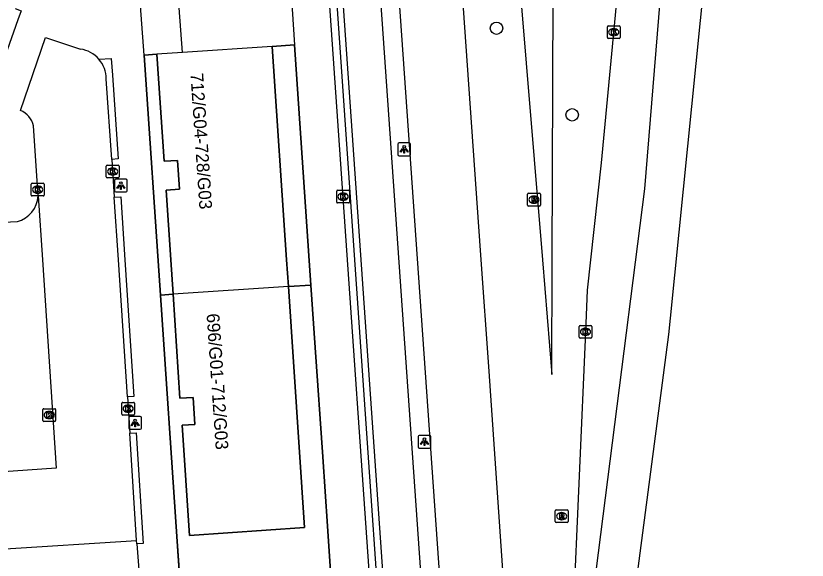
# Model space of a CAD drawing. Extents: x 161253 to 161848, y 384872 to 385383.
# Drawn here: x 161781 to 161843, y 385226.4 to 385269.1 of the extents above; entities that cross this region are included whole.
import ezdxf

# ---------------------------------------------------------------- set-up
doc = ezdxf.new("R2010")
doc.units = 0
for name, color, linetype in [('IMGEO_Berm_groen', 7, 'Continuous'), ('IMGEO_Boom', 7, 'Continuous'), ('IMGEO_Fietspad_open', 7, 'Continuous'), ('IMGEO_Groenvoorziening', 7, 'Continuous'), ('IMGEO_Kolk', 7, 'Continuous'), ('IMGEO_Lichtpunt', 7, 'Continuous'), ('IMGEO_Muur', 7, 'Continuous'), ('IMGEO_Pand', 7, 'Continuous'), ('IMGEO_Pand_nummerreeks', 7, 'Continuous'), ('IMGEO_Pand_overbouw', 7, 'Continuous'), ('IMGEO_Rijbaan_lokaal_open', 7, 'Continuous'), ('IMGEO_Rijbaan_regionaal_gesloten', 7, 'Continuous'), ('IMGEO_Rioolput', 7, 'Continuous'), ('IMGEO_Voetpad_open', 7, 'Continuous')]:
    doc.layers.add(name, color=color, linetype=linetype)

msp = doc.modelspace()

# ---------------------------------------------------------------- linework, layer by layer
at = {"layer": 'IMGEO_Berm_groen'}
msp.add_lwpolyline([(161816.166, 385334.74), (161815.82, 385327.746), (161822.257, 385250), (161823.001, 385241.01), (161823.031, 385250), (161823.145, 385284.452), (161822.02, 385322.916), (161823.326, 385328.009), (161824.925, 385332.823), (161826.852, 385340.216), (161827.714, 385344.496), (161827.957, 385346.444)], dxfattribs=at)
at = {"layer": 'IMGEO_Boom'}
for centre in [(161818.659, 385268.157), (161824.59, 385261.368)]:
    msp.add_circle(centre, 0.489, dxfattribs=at)
at = {"layer": 'IMGEO_Fietspad_open'}
for points in [[(161799.416, 385136.747), (161804.851, 385161.932), (161805.798, 385165.717), (161808.364, 385173.407), (161809.023, 385177.396), (161809.973, 385187.32), (161810.725, 385197.446), (161810.795, 385201.149), (161811.014, 385207.171), (161808.054, 385250), (161801.247, 385347.561), (161799.482, 385356.188)], [(161806.85, 385157.128), (161812.029, 385175.625), (161814.159, 385203.908), (161813.652, 385212.427), (161806.814, 385309.979), (161806.751, 385311.045)]]:
    msp.add_lwpolyline(points, dxfattribs=at)
at = {"layer": 'IMGEO_Groenvoorziening'}
msp.add_lwpolyline([(161794.035, 385266.255), (161792.717, 385284.125)], dxfattribs=at)
at = {"layer": 'IMGEO_Kolk'}
for p, q in [((161827.343, 385267.422), (161827.343, 385268.274)), ((161827.418, 385268.348), (161828.27, 385268.348)), ((161827.831, 385268.128), (161827.856, 385268.128)), ((161828.344, 385268.274), (161828.344, 385267.422)), ((161827.854, 385267.568), (161827.829, 385267.568)), ((161828.27, 385267.348), (161827.418, 385267.348)), ((161788.069, 385256.494), (161788.069, 385257.346)), ((161788.144, 385257.42), (161788.996, 385257.42)), ((161788.557, 385257.2), (161788.582, 385257.2)), ((161789.07, 385257.346), (161789.07, 385256.494)), ((161788.996, 385256.42), (161788.144, 385256.42)), ((161788.58, 385256.64), (161788.555, 385256.64)), ((161782.195, 385255.079), (161782.195, 385255.931)), ((161782.27, 385256.005), (161783.122, 385256.005)), ((161782.683, 385255.785), (161782.708, 385255.785)), ((161783.196, 385255.931), (161783.196, 385255.079)), ((161783.122, 385255.005), (161782.27, 385255.005)), ((161782.706, 385255.225), (161782.681, 385255.225)), ((161806.129, 385254.528), (161806.129, 385255.38)), ((161806.204, 385255.454), (161807.056, 385255.454)), ((161806.617, 385255.234), (161806.642, 385255.234)), ((161807.13, 385255.38), (161807.13, 385254.528)), ((161807.056, 385254.454), (161806.204, 385254.454)), ((161806.64, 385254.674), (161806.615, 385254.674)), ((161825.131, 385243.929), (161825.131, 385244.781)), ((161825.206, 385244.855), (161826.058, 385244.855)), ((161825.619, 385244.635), (161825.644, 385244.635)), ((161826.132, 385244.781), (161826.132, 385243.929)), ((161826.058, 385243.855), (161825.206, 385243.855)), ((161825.642, 385244.075), (161825.617, 385244.075)), ((161783.102, 385237.398), (161783.102, 385238.25)), ((161783.177, 385238.324), (161784.029, 385238.324)), ((161784.103, 385238.25), (161784.103, 385237.398)), ((161789.285, 385237.896), (161789.285, 385238.748)), ((161789.36, 385238.822), (161790.212, 385238.822)), ((161789.773, 385238.602), (161789.798, 385238.602)), ((161790.286, 385238.748), (161790.286, 385237.896)), ((161783.59, 385238.104), (161783.615, 385238.104)), ((161790.212, 385237.822), (161789.36, 385237.822)), ((161789.796, 385238.042), (161789.771, 385238.042)), ((161784.029, 385237.324), (161783.177, 385237.324)), ((161783.613, 385237.544), (161783.588, 385237.544))]:
    msp.add_line(p, q, dxfattribs=at)
for points in [[(161827.343, 385267.422), (161827.343, 385268.274)], [(161827.418, 385268.348), (161828.27, 385268.348)], [(161827.664, 385268.048), (161827.787, 385268.048), (161827.787, 385267.897), (161827.917, 385268.048), (161828.081, 385268.048), (161827.935, 385267.897), (161828.088, 385267.648), (161827.936, 385267.648), (161827.851, 385267.812), (161827.787, 385267.745), (161827.787, 385267.648), (161827.664, 385267.648), (161827.664, 385268.048)], [(161828.344, 385268.274), (161828.344, 385267.422)], [(161828.27, 385267.348), (161827.418, 385267.348)], [(161788.069, 385256.494), (161788.069, 385257.346)], [(161788.144, 385257.42), (161788.996, 385257.42)], [(161788.39, 385257.12), (161788.513, 385257.12), (161788.513, 385256.969), (161788.643, 385257.12), (161788.807, 385257.12), (161788.661, 385256.969), (161788.814, 385256.72), (161788.662, 385256.72), (161788.577, 385256.884), (161788.513, 385256.817), (161788.513, 385256.72), (161788.39, 385256.72), (161788.39, 385257.12)], [(161789.07, 385257.346), (161789.07, 385256.494)], [(161788.996, 385256.42), (161788.144, 385256.42)], [(161782.195, 385255.079), (161782.195, 385255.931)], [(161782.27, 385256.005), (161783.122, 385256.005)], [(161782.516, 385255.705), (161782.639, 385255.705), (161782.639, 385255.554), (161782.769, 385255.705), (161782.933, 385255.705), (161782.787, 385255.554), (161782.94, 385255.305), (161782.788, 385255.305), (161782.703, 385255.469), (161782.639, 385255.402), (161782.639, 385255.305), (161782.516, 385255.305), (161782.516, 385255.705)], [(161783.196, 385255.931), (161783.196, 385255.079)], [(161783.122, 385255.005), (161782.27, 385255.005)], [(161806.129, 385254.528), (161806.129, 385255.38)], [(161806.204, 385255.454), (161807.056, 385255.454)], [(161806.45, 385255.154), (161806.573, 385255.154), (161806.573, 385255.003), (161806.703, 385255.154), (161806.867, 385255.154), (161806.721, 385255.003), (161806.874, 385254.754), (161806.722, 385254.754), (161806.637, 385254.918), (161806.573, 385254.851), (161806.573, 385254.754), (161806.45, 385254.754), (161806.45, 385255.154)], [(161807.13, 385255.38), (161807.13, 385254.528)], [(161807.056, 385254.454), (161806.204, 385254.454)], [(161825.131, 385243.929), (161825.131, 385244.781)], [(161825.206, 385244.855), (161826.058, 385244.855)], [(161825.452, 385244.555), (161825.575, 385244.555), (161825.575, 385244.404), (161825.705, 385244.555), (161825.869, 385244.555), (161825.723, 385244.404), (161825.876, 385244.155), (161825.724, 385244.155), (161825.639, 385244.319), (161825.575, 385244.252), (161825.575, 385244.155), (161825.452, 385244.155), (161825.452, 385244.555)], [(161826.132, 385244.781), (161826.132, 385243.929)], [(161826.058, 385243.855), (161825.206, 385243.855)], [(161783.102, 385237.398), (161783.102, 385238.25)], [(161783.177, 385238.324), (161784.029, 385238.324)], [(161784.103, 385238.25), (161784.103, 385237.398)], [(161789.285, 385237.896), (161789.285, 385238.748)], [(161789.36, 385238.822), (161790.212, 385238.822)], [(161789.606, 385238.522), (161789.729, 385238.522), (161789.729, 385238.371), (161789.859, 385238.522), (161790.023, 385238.522), (161789.877, 385238.371), (161790.03, 385238.122), (161789.878, 385238.122), (161789.793, 385238.286), (161789.729, 385238.219), (161789.729, 385238.122), (161789.606, 385238.122), (161789.606, 385238.522)], [(161790.286, 385238.748), (161790.286, 385237.896)], [(161783.423, 385238.024), (161783.546, 385238.024), (161783.546, 385237.873), (161783.676, 385238.024), (161783.84, 385238.024), (161783.694, 385237.873), (161783.847, 385237.624), (161783.695, 385237.624), (161783.61, 385237.788), (161783.546, 385237.721), (161783.546, 385237.624), (161783.423, 385237.624), (161783.423, 385238.024)], [(161790.212, 385237.822), (161789.36, 385237.822)], [(161784.029, 385237.324), (161783.177, 385237.324)]]:
    msp.add_lwpolyline(points, dxfattribs=at)
for centre, start, end in [((161827.42, 385268.272), 91.55205, 178.44795), ((161827.42, 385268.272), 91.55205, 178.44795), ((161828.268, 385268.272), 1.55205, 88.44795), ((161828.268, 385268.272), 1.55205, 88.44795), ((161827.42, 385267.424), 181.55205, 268.44795), ((161827.42, 385267.424), 181.55205, 268.44795), ((161828.268, 385267.424), 271.55205, 358.44795), ((161828.268, 385267.424), 271.55205, 358.44795), ((161788.146, 385257.344), 91.55205, 178.44795), ((161788.146, 385257.344), 91.55205, 178.44795), ((161788.994, 385257.344), 1.55205, 88.44795), ((161788.994, 385257.344), 1.55205, 88.44795), ((161788.146, 385256.496), 181.55205, 268.44795), ((161788.146, 385256.496), 181.55205, 268.44795), ((161788.994, 385256.496), 271.55205, 358.44795), ((161788.994, 385256.496), 271.55205, 358.44795), ((161782.272, 385255.929), 91.55205, 178.44795), ((161782.272, 385255.929), 91.55205, 178.44795), ((161783.12, 385255.929), 1.55205, 88.44795), ((161783.12, 385255.929), 1.55205, 88.44795), ((161782.272, 385255.081), 181.55205, 268.44795), ((161782.272, 385255.081), 181.55205, 268.44795), ((161783.12, 385255.081), 271.55205, 358.44795), ((161783.12, 385255.081), 271.55205, 358.44795), ((161806.206, 385255.378), 91.55205, 178.44795), ((161806.206, 385255.378), 91.55205, 178.44795), ((161807.054, 385255.378), 1.55205, 88.44795), ((161807.054, 385255.378), 1.55205, 88.44795), ((161806.206, 385254.53), 181.55205, 268.44795), ((161806.206, 385254.53), 181.55205, 268.44795), ((161807.054, 385254.53), 271.55205, 358.44795), ((161807.054, 385254.53), 271.55205, 358.44795), ((161825.208, 385244.779), 91.55205, 178.44795), ((161825.208, 385244.779), 91.55205, 178.44795), ((161826.056, 385244.779), 1.55205, 88.44795), ((161826.056, 385244.779), 1.55205, 88.44795), ((161825.208, 385243.931), 181.55205, 268.44795), ((161825.208, 385243.931), 181.55205, 268.44795), ((161826.056, 385243.931), 271.55205, 358.44795), ((161826.056, 385243.931), 271.55205, 358.44795), ((161783.179, 385238.248), 91.55205, 178.44795), ((161783.179, 385238.248), 91.55205, 178.44795), ((161784.027, 385238.248), 1.55205, 88.44795), ((161784.027, 385238.248), 1.55205, 88.44795), ((161789.362, 385238.746), 91.55205, 178.44795), ((161789.362, 385238.746), 91.55205, 178.44795), ((161790.21, 385238.746), 1.55205, 88.44795), ((161790.21, 385238.746), 1.55205, 88.44795), ((161789.362, 385237.898), 181.55205, 268.44795), ((161789.362, 385237.898), 181.55205, 268.44795), ((161790.21, 385237.898), 271.55205, 358.44795), ((161790.21, 385237.898), 271.55205, 358.44795), ((161783.179, 385237.4), 181.55205, 268.44795), ((161783.179, 385237.4), 181.55205, 268.44795), ((161784.027, 385237.4), 271.55205, 358.44795), ((161784.027, 385237.4), 271.55205, 358.44795)]:
    msp.add_arc(centre, 0.0765, start, end, dxfattribs=at)
for centre, major_axis, ratio, start_param, end_param in [((161827.83, 385267.848), (-0.387, 0.002), 0.722429, 4.712389, 7.853982), ((161827.855, 385267.848), (-0.39, 0.002), 0.717154, 1.570796, 4.712389), ((161788.556, 385256.92), (-0.387, 0.002), 0.722429, 4.712389, 7.853982), ((161788.581, 385256.92), (-0.39, 0.002), 0.717154, 1.570796, 4.712389), ((161782.682, 385255.505), (-0.387, 0.002), 0.722429, 4.712389, 7.853982), ((161782.707, 385255.505), (-0.39, 0.002), 0.717154, 1.570796, 4.712389), ((161806.616, 385254.954), (-0.387, 0.002), 0.722429, 4.712389, 7.853982), ((161806.641, 385254.954), (-0.39, 0.002), 0.717154, 1.570796, 4.712389), ((161825.618, 385244.355), (-0.387, 0.002), 0.722429, 4.712389, 7.853982), ((161825.643, 385244.355), (-0.39, 0.002), 0.717154, 1.570796, 4.712389), ((161789.772, 385238.322), (-0.387, 0.002), 0.722429, 4.712389, 7.853982), ((161789.797, 385238.322), (-0.39, 0.002), 0.717154, 1.570796, 4.712389), ((161783.589, 385237.824), (-0.387, 0.002), 0.722429, 4.712389, 7.853982), ((161783.614, 385237.824), (-0.39, 0.002), 0.717154, 1.570796, 4.712389)]:
    msp.add_ellipse(centre, major_axis=major_axis, ratio=ratio, start_param=start_param, end_param=end_param, dxfattribs=at)
at = {"layer": 'IMGEO_Lichtpunt'}
for p, q in [((161810.925, 385259.064), (161810.925, 385258.257)), ((161810.925, 385259.064), (161810.925, 385258.257)), ((161811.827, 385259.159), (161811.019, 385259.159)), ((161811.827, 385259.159), (161811.019, 385259.159)), ((161811.921, 385258.257), (161811.921, 385259.064)), ((161811.921, 385258.257), (161811.921, 385259.064)), ((161811.019, 385258.163), (161811.827, 385258.163)), ((161811.019, 385258.163), (161811.827, 385258.163)), ((161789.622, 385256.317), (161788.814, 385256.317)), ((161789.622, 385256.317), (161788.814, 385256.317)), ((161788.72, 385256.222), (161788.72, 385255.415)), ((161788.72, 385256.222), (161788.72, 385255.415)), ((161789.716, 385255.415), (161789.716, 385256.222)), ((161789.716, 385255.415), (161789.716, 385256.222)), ((161788.814, 385255.321), (161789.622, 385255.321)), ((161788.814, 385255.321), (161789.622, 385255.321)), ((161790.733, 385237.712), (161789.925, 385237.712)), ((161790.733, 385237.712), (161789.925, 385237.712)), ((161789.831, 385237.617), (161789.831, 385236.81)), ((161789.831, 385237.617), (161789.831, 385236.81)), ((161790.827, 385236.81), (161790.827, 385237.617)), ((161790.827, 385236.81), (161790.827, 385237.617)), ((161789.925, 385236.716), (161790.733, 385236.716)), ((161789.925, 385236.716), (161790.733, 385236.716)), ((161812.506, 385236.14), (161812.506, 385235.333)), ((161812.506, 385236.14), (161812.506, 385235.333)), ((161813.408, 385236.235), (161812.6, 385236.235)), ((161813.408, 385236.235), (161812.6, 385236.235)), ((161813.502, 385235.333), (161813.502, 385236.14)), ((161813.502, 385235.333), (161813.502, 385236.14)), ((161812.6, 385235.239), (161813.408, 385235.239)), ((161812.6, 385235.239), (161813.408, 385235.239))]:
    msp.add_line(p, q, dxfattribs=at)
for points in [[(161811.299, 385258.728), (161811.338, 385258.7), (161811.15, 385258.438), (161811.112, 385258.465), (161811.299, 385258.728)], [(161811.511, 385258.7), (161811.549, 385258.727), (161811.736, 385258.465), (161811.697, 385258.437), (161811.511, 385258.7)], [(161811.401, 385258.68), (161811.448, 385258.68), (161811.448, 385258.358), (161811.401, 385258.358), (161811.401, 385258.68)], [(161789.094, 385255.886), (161789.133, 385255.858), (161788.945, 385255.596), (161788.907, 385255.623), (161789.094, 385255.886)], [(161789.196, 385255.838), (161789.243, 385255.838), (161789.243, 385255.516), (161789.196, 385255.516), (161789.196, 385255.838)], [(161789.306, 385255.858), (161789.344, 385255.885), (161789.531, 385255.623), (161789.492, 385255.595), (161789.306, 385255.858)], [(161790.205, 385237.281), (161790.244, 385237.253), (161790.056, 385236.991), (161790.018, 385237.018), (161790.205, 385237.281)], [(161790.307, 385237.233), (161790.354, 385237.233), (161790.354, 385236.911), (161790.307, 385236.911), (161790.307, 385237.233)], [(161790.417, 385237.253), (161790.455, 385237.28), (161790.642, 385237.018), (161790.603, 385236.99), (161790.417, 385237.253)], [(161812.88, 385235.804), (161812.919, 385235.776), (161812.731, 385235.514), (161812.693, 385235.541), (161812.88, 385235.804)], [(161813.092, 385235.776), (161813.13, 385235.803), (161813.317, 385235.541), (161813.278, 385235.513), (161813.092, 385235.776)], [(161812.982, 385235.756), (161813.029, 385235.756), (161813.029, 385235.434), (161812.982, 385235.434), (161812.982, 385235.756)]]:
    msp.add_lwpolyline(points, dxfattribs=at)
for centre in [(161811.424, 385258.862), (161789.219, 385256.02), (161790.33, 385237.415), (161813.005, 385235.938)]:
    msp.add_circle(centre, 0.0994, dxfattribs=at)
for centre, start, end in [((161811.019, 385259.064), 90, 180), ((161811.019, 385259.064), 90, 180), ((161811.827, 385259.064), 0, 90), ((161811.827, 385259.064), 0, 90), ((161811.019, 385258.257), 180, 270), ((161811.019, 385258.257), 180, 270), ((161811.827, 385258.257), 270, 0), ((161811.827, 385258.257), 270, 360), ((161788.814, 385256.222), 90, 180), ((161788.814, 385256.222), 90, 180), ((161789.622, 385256.222), 0, 90), ((161789.622, 385256.222), 0, 90), ((161788.814, 385255.415), 180, 270), ((161788.814, 385255.415), 180, 270), ((161789.622, 385255.415), 270, 0), ((161789.622, 385255.415), 270, 360), ((161789.925, 385237.617), 90, 180), ((161789.925, 385237.617), 90, 180), ((161790.733, 385237.617), 0, 90), ((161790.733, 385237.617), 0, 90), ((161789.925, 385236.81), 180, 270), ((161789.925, 385236.81), 180, 270), ((161790.733, 385236.81), 270, 0), ((161790.733, 385236.81), 270, 360), ((161812.6, 385236.14), 90, 180), ((161812.6, 385236.14), 90, 180), ((161813.408, 385236.14), 0, 90), ((161813.408, 385236.14), 0, 90), ((161812.6, 385235.333), 180, 270), ((161812.6, 385235.333), 180, 270), ((161813.408, 385235.333), 270, 0), ((161813.408, 385235.333), 270, 360)]:
    msp.add_arc(centre, 0.0946, start, end, dxfattribs=at)
at = {"layer": 'IMGEO_Muur'}
msp.add_lwpolyline([(161809.266, 385191.488), (161809.957, 385207.224), (161806.977, 385250), (161800.175, 385347.621), (161800.798, 385347.634), (161807.52, 385250), (161810.465, 385207.275), (161809.778, 385192.126), (161808.589, 385177.868), (161808.119, 385177.946)], dxfattribs=at)
at = {"layer": 'IMGEO_Pand'}
for points in [[(161794.035, 385266.255), (161792.035, 385266.121)], [(161801.083, 385266.729), (161794.035, 385266.255)], [(161802.347, 385247.903), (161802.206, 385250), (161801.083, 385266.729)], [(161792.035, 385266.121), (161792.599, 385257.725), (161793.648, 385257.796), (161793.8, 385255.525), (161792.753, 385255.455), (161793.119, 385250), (161793.301, 385247.294)], [(161802.347, 385247.903), (161793.301, 385247.294)], [(161793.301, 385247.294), (161793.848, 385239.143), (161794.874, 385239.212), (161795.016, 385237.092), (161794.006, 385237.024), (161794.586, 385228.39), (161803.617, 385228.996), (161802.347, 385247.903)]]:
    msp.add_lwpolyline(points, dxfattribs=at)
at = {"layer": 'IMGEO_Pand_overbouw'}
for points in [[(161801.083, 385266.729), (161802.206, 385250), (161802.347, 385247.903), (161804.116, 385248.022), (161802.83, 385266.843)], [(161792.035, 385266.121), (161791.041, 385266.055), (161792.323, 385247.228), (161793.301, 385247.294), (161793.119, 385250), (161792.753, 385255.455), (161793.8, 385255.525), (161793.648, 385257.796), (161792.599, 385257.725)], [(161794.183, 385219.903), (161794.528, 385219.927), (161799.049, 385220.235), (161799.658, 385220.277), (161800.025, 385220.302), (161802.431, 385220.466), (161802.511, 385219.288), (161806.062, 385219.53), (161805.728, 385224.419), (161805.407, 385229.116), (161805.036, 385234.554), (161804.45, 385243.135), (161804.116, 385248.022), (161802.347, 385247.903), (161803.617, 385228.996), (161794.586, 385228.39), (161794.006, 385237.024), (161795.016, 385237.092), (161794.874, 385239.212), (161793.848, 385239.143), (161793.301, 385247.294), (161792.323, 385247.228), (161793.611, 385228.31), (161794.123, 385220.789)]]:
    msp.add_lwpolyline(points, close=True, dxfattribs=at)
at = {"layer": 'IMGEO_Rijbaan_lokaal_open'}
for points in [[(161781.344, 385261.707), (161783.307, 385267.425), (161786.041, 385266.521)], [(161788.495, 385257.871), (161788.067, 385264.181), (161788.058, 385264.391), (161788.031, 385264.599), (161787.985, 385264.804), (161787.922, 385265.004), (161787.84, 385265.198), (161787.742, 385265.383), (161787.627, 385265.559), (161787.499, 385265.722)], [(161782.73, 385255.008), (161782.367, 385260.501)], [(161788.495, 385257.871), (161788.697, 385254.902)], [(161782.73, 385255.008), (161783.061, 385250), (161784.141, 385233.648), (161779.623, 385233.341)], [(161789.723, 385239.256), (161789.03, 385250), (161788.697, 385254.902)], [(161789.723, 385239.256), (161789.907, 385236.407)], [(161790.451, 385227.985), (161789.907, 385236.407)], [(161769.034, 385226.639), (161790.451, 385227.985)]]:
    msp.add_lwpolyline(points, dxfattribs=at)
for centre, radius, start, end in [((161785.709, 385264.185), 2.36, 40.64908, 81.90447), ((161780.687, 385260.112), 1.725, 13.01936, 67.59377)]:
    msp.add_arc(centre, radius, start, end, dxfattribs=at)
at = {"layer": 'IMGEO_Rijbaan_regionaal_gesloten'}
for points in [[(161843.005, 385383.208), (161841.331, 385358.305), (161840.149, 385339.983), (161835.302, 385275.534), (161832.26, 385245.433), (161832.129, 385244.136), (161827.354, 385207.649), (161824.158, 385190.185), (161821.142, 385173.699), (161813.159, 385133.822)], [(161820.763, 385202.038), (161819.519, 385220.338), (161818.054, 385241.62), (161817.448, 385250), (161811.078, 385340.796), (161810.451, 385350.052), (161810.363, 385351.383)], [(161836.528, 385338.731), (161836.173, 385328.205), (161830.26, 385255.555), (161825.195, 385215.738), (161824.131, 385211.474)], [(161832.467, 385327.037), (161831.359, 385311.824), (161829.723, 385290.378), (161828.725, 385278.097), (161828.314, 385273.073), (161826.86, 385257.604), (161826.033, 385250), (161825.773, 385247.608), (161825.632, 385244.355), (161824.63, 385221.78), (161824.131, 385211.474)], [(161807.935, 385314.055), (161807.968, 385313.899), (161808.13, 385311.584), (161815.94, 385200.171)]]:
    msp.add_lwpolyline(points, dxfattribs=at)
at = {"layer": 'IMGEO_Rioolput'}
for p, q in [((161821.097, 385254.287), (161821.097, 385255.139)), ((161821.172, 385255.213), (161822.024, 385255.213)), ((161822.098, 385255.139), (161822.098, 385254.287)), ((161821.608, 385254.433), (161821.583, 385254.433)), ((161821.585, 385254.993), (161821.61, 385254.993)), ((161822.024, 385254.213), (161821.172, 385254.213)), ((161823.263, 385229.467), (161823.263, 385230.319)), ((161823.338, 385230.393), (161824.19, 385230.393)), ((161824.264, 385230.319), (161824.264, 385229.467)), ((161823.774, 385229.613), (161823.749, 385229.613)), ((161823.751, 385230.173), (161823.776, 385230.173)), ((161824.19, 385229.393), (161823.338, 385229.393))]:
    msp.add_line(p, q, dxfattribs=at)
for points in [[(161821.097, 385254.287), (161821.097, 385255.139)], [(161821.172, 385255.213), (161822.024, 385255.213)], [(161822.098, 385255.139), (161822.098, 385254.287)], [(161821.686, 385254.911), (161821.434, 385254.913), (161821.434, 385254.513)], [(161821.434, 385254.513), (161821.558, 385254.513), (161821.558, 385254.675), (161821.569, 385254.675)], [(161821.612, 385254.832), (161821.558, 385254.832), (161821.558, 385254.751)], [(161821.558, 385254.751), (161821.61, 385254.751)], [(161821.616, 385254.646), (161821.687, 385254.513), (161821.827, 385254.513), (161821.762, 385254.639)], [(161822.024, 385254.213), (161821.172, 385254.213)], [(161823.263, 385229.467), (161823.263, 385230.319)], [(161823.338, 385230.393), (161824.19, 385230.393)], [(161824.264, 385230.319), (161824.264, 385229.467)], [(161823.852, 385230.091), (161823.6, 385230.093), (161823.6, 385229.693)], [(161823.6, 385229.693), (161823.724, 385229.693), (161823.724, 385229.855), (161823.735, 385229.855)], [(161823.778, 385230.012), (161823.724, 385230.012), (161823.724, 385229.931)], [(161823.724, 385229.931), (161823.776, 385229.931)], [(161823.782, 385229.826), (161823.853, 385229.693), (161823.993, 385229.693), (161823.928, 385229.819)], [(161824.19, 385229.393), (161823.338, 385229.393)]]:
    msp.add_lwpolyline(points, dxfattribs=at)
for centre, radius, start, end in [((161821.174, 385255.137), 0.0765, 91.55205, 178.44795), ((161821.174, 385255.137), 0.0765, 91.55205, 178.44795), ((161822.022, 385255.137), 0.0765, 1.55205, 88.44795), ((161822.022, 385255.137), 0.0765, 1.55205, 88.44795), ((161821.568, 385254.622), 0.0533, 26.02933, 88.69889), ((161821.594, 385254.94), 0.19, 274.7715, 282.96867), ((161821.618, 385254.736), 0.0964, 77.00612, 93.18647), ((161821.632, 385254.793), 0.0378, 276.66336, 79.67722), ((161821.685, 385254.801), 0.109, 350.36119, 89.41601), ((161821.683, 385254.801), 0.112, 277.58423, 350.98172), ((161821.667, 385254.586), 0.108, 29.51342, 73.79051), ((161821.174, 385254.289), 0.0765, 181.55205, 268.44795), ((161821.174, 385254.289), 0.0765, 181.55205, 268.44795), ((161822.022, 385254.289), 0.0765, 271.55205, 358.44795), ((161822.022, 385254.289), 0.0765, 271.55205, 358.44795), ((161823.34, 385230.317), 0.0765, 91.55205, 178.44795), ((161823.34, 385230.317), 0.0765, 91.55205, 178.44795), ((161824.188, 385230.317), 0.0765, 1.55205, 88.44795), ((161824.188, 385230.317), 0.0765, 1.55205, 88.44795), ((161823.734, 385229.802), 0.0533, 26.02933, 88.69889), ((161823.76, 385230.12), 0.19, 274.7715, 282.96867), ((161823.784, 385229.916), 0.0964, 77.00612, 93.18647), ((161823.798, 385229.973), 0.0378, 276.66336, 79.67722), ((161823.851, 385229.981), 0.109, 350.36119, 89.41601), ((161823.849, 385229.981), 0.112, 277.58423, 350.98172), ((161823.833, 385229.766), 0.108, 29.51342, 73.79051), ((161823.34, 385229.469), 0.0765, 181.55205, 268.44795), ((161823.34, 385229.469), 0.0765, 181.55205, 268.44795), ((161824.188, 385229.469), 0.0765, 271.55205, 358.44795), ((161824.188, 385229.469), 0.0765, 271.55205, 358.44795)]:
    msp.add_arc(centre, radius, start, end, dxfattribs=at)
for centre, major_axis, ratio, start_param, end_param in [((161821.584, 385254.713), (-0.387, 0.002), 0.722429, 4.712389, 7.853982), ((161821.609, 385254.713), (-0.39, 0.002), 0.717154, 1.570796, 4.712389), ((161823.75, 385229.893), (-0.387, 0.002), 0.722429, 4.712389, 7.853982), ((161823.775, 385229.893), (-0.39, 0.002), 0.717154, 1.570796, 4.712389)]:
    msp.add_ellipse(centre, major_axis=major_axis, ratio=ratio, start_param=start_param, end_param=end_param, dxfattribs=at)
at = {"layer": 'IMGEO_Voetpad_open'}
for points in [[(161801.666, 385284.479), (161802.83, 385266.843)], [(161791.041, 385266.055), (161789.717, 385284.007)], [(161780.943, 385269.693), (161781.403, 385269.529), (161781.152, 385268.827), (161778.441, 385261.241), (161777.978, 385261.406)], [(161801.083, 385266.729), (161802.83, 385266.843)], [(161802.83, 385266.843), (161804.116, 385248.022), (161804.45, 385243.135), (161805.036, 385234.554), (161805.407, 385229.116), (161805.728, 385224.419), (161806.062, 385219.53)], [(161787.499, 385265.722), (161788.457, 385265.788), (161788.547, 385264.483), (161789.001, 385257.906), (161788.495, 385257.871)], [(161791.041, 385266.055), (161792.035, 385266.121)], [(161794.183, 385219.903), (161793.611, 385228.31), (161792.323, 385247.228), (161791.041, 385266.055)], [(161788.697, 385254.902), (161789.205, 385254.935), (161789.526, 385250), (161790.222, 385239.288), (161789.723, 385239.256)], [(161779.623, 385233.341), (161778.524, 385250), (161778.334, 385252.875), (161781.105, 385253)], [(161789.907, 385236.407), (161790.405, 385236.439), (161790.968, 385227.75), (161790.47, 385227.718)], [(161790.47, 385227.718), (161790.768, 385223.612), (161769.376, 385222.155), (161769.034, 385226.639)], [(161790.47, 385227.718), (161790.451, 385227.985)]]:
    msp.add_lwpolyline(points, dxfattribs=at)
msp.add_arc((161780.548, 385255.112), 2.185, 284.77483, 357.26124, dxfattribs=at)

# ---------------------------------------------------------------- texts
at = {"layer": 'IMGEO_Pand_nummerreeks'}
for s, rotation, p in [('712/G04-728/G03', 273.84608, (161794.662, 385264.614)), ('696/G01-712/G03', 273.88962, (161795.931, 385245.759))]:
    msp.add_text(s, height=1, rotation=rotation, dxfattribs=at).set_placement(p)

doc.saveas('drawing.dxf')
